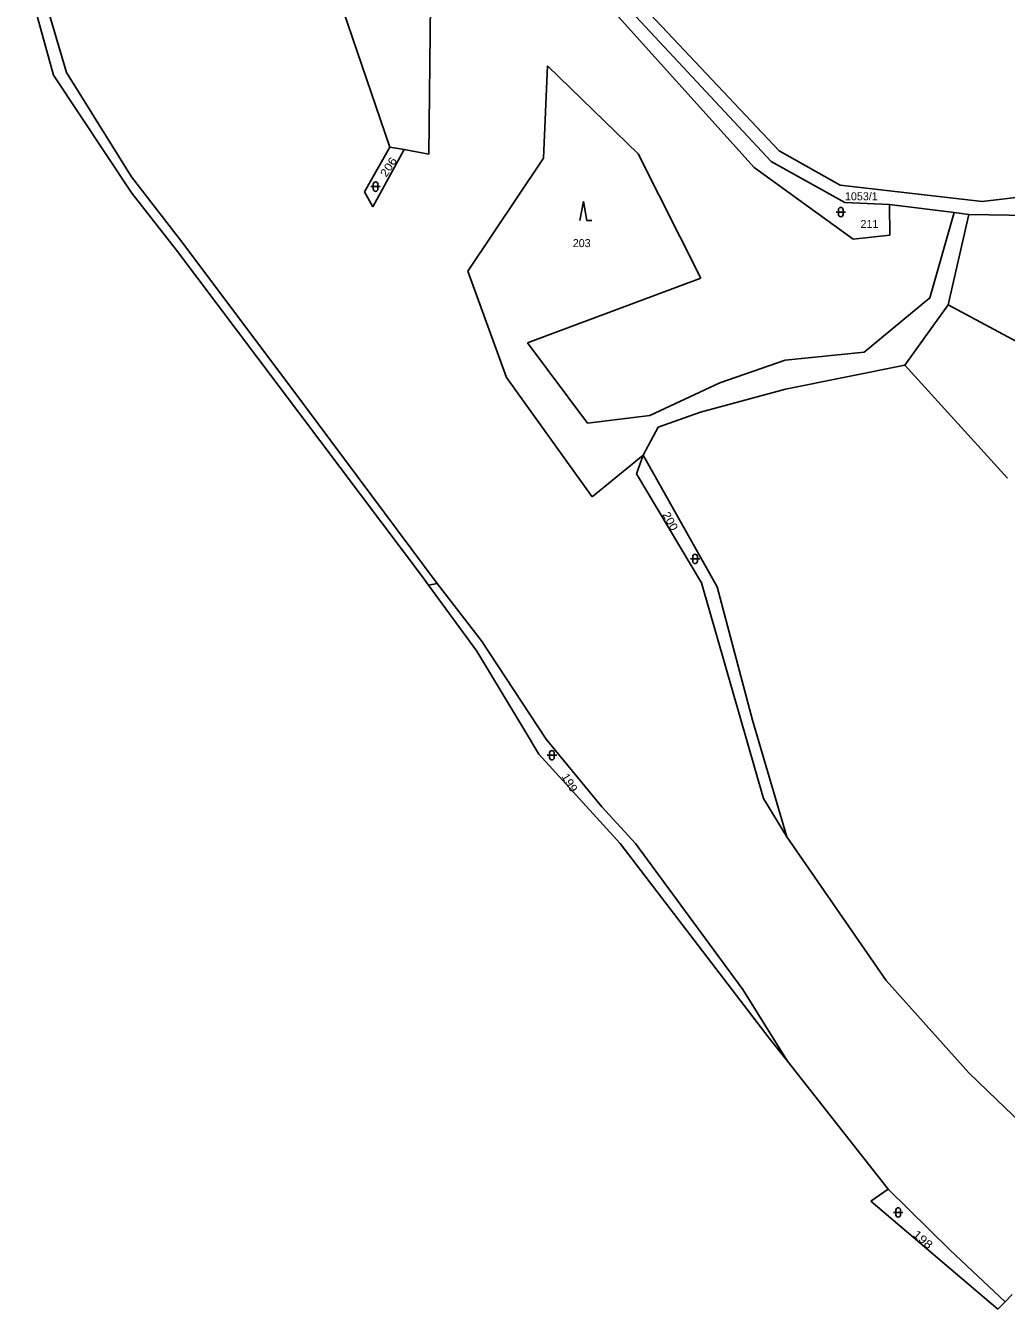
# Model space of a CAD drawing. Extents: x -744132 to -742433, y -984679 to -982287.
# Drawn here: x -743199.3 to -742991, y -984512.6 to -984240 of the extents above; entities that cross this region are included whole.
import ezdxf

# ---------------------------------------------------------------- set-up
doc = ezdxf.new("R2010")
doc.units = 0
doc.header["$LTSCALE"] = 0.68
doc.layers.add('1', color=7, linetype='Continuous', lineweight=25)
doc.layers.add('3', color=7, linetype='Continuous', lineweight=25)
doc.layers.add('2', color=7, linetype='Continuous')

msp = doc.modelspace()

# ---------------------------------------------------------------- linework, layer by layer
at = {"layer": '1'}
for p, q in [((-743190.62, -984249.97), (-743198.06, -984224.85)), ((-743079.78, -984227.24), (-743040.94, -984268.88)), ((-743199.32, -984229.05), (-743193.39, -984250.57)), ((-743134.8, -984228.15), (-743121.95, -984265.83)), ((-743073.53, -984230.29), (-743039.24, -984266.63)), ((-743079.06, -984231.79), (-743044.54, -984270.13)), ((-743113.67, -984267.35), (-743113.33, -984235.31)), ((-743088.46, -984248.53), (-743089.29, -984268.15)), ((-743069.21, -984267.24), (-743088.46, -984248.53)), ((-743193.39, -984250.57), (-743176.73, -984275.57)), ((-743176.87, -984272.12), (-743190.62, -984249.97)), ((-743121.95, -984265.83), (-743127.33, -984275.33)), ((-743125.59, -984278.51), (-743118.89, -984266.36)), ((-743121.95, -984265.83), (-743118.89, -984266.36)), ((-743118.89, -984266.36), (-743113.67, -984267.35)), ((-743089.29, -984268.15), (-743105.41, -984292.13)), ((-743055.92, -984293.65), (-743069.21, -984267.24)), ((-743039.24, -984266.63), (-743026.29, -984273.89)), ((-743044.54, -984270.13), (-743023.52, -984285.4)), ((-743040.94, -984268.88), (-743025.3, -984277.56)), ((-743165.92, -984286.22), (-743176.87, -984272.12)), ((-743026.29, -984273.89), (-742996.15, -984277.35)), ((-743176.73, -984275.57), (-743167.29, -984287.69)), ((-743127.33, -984275.33), (-743125.59, -984278.51)), ((-742996.15, -984277.35), (-742986.54, -984276.26)), ((-743025.3, -984277.56), (-743015.82, -984277.98)), ((-743015.7, -984284.55), (-743015.82, -984277.98)), ((-743015.82, -984277.98), (-743002.06, -984279.73)), ((-743002.06, -984279.73), (-743007.23, -984297.79)), ((-743003.32, -984299.32), (-742998.92, -984280.13)), ((-743002.06, -984279.73), (-742998.92, -984280.13)), ((-742998.92, -984280.13), (-742986.17, -984280.32)), ((-743023.52, -984285.4), (-743015.7, -984284.55)), ((-743140.1, -984320.72), (-743165.92, -984286.22)), ((-743167.29, -984287.69), (-743115.24, -984356.81)), ((-743105.41, -984292.13), (-743097.16, -984314.76)), ((-743092.72, -984307.41), (-743055.92, -984293.65)), ((-743007.23, -984297.79), (-743021.17, -984309.37)), ((-743012.53, -984312.09), (-743003.32, -984299.32)), ((-743003.32, -984299.32), (-742985.75, -984308.73)), ((-743079.93, -984324.44), (-743092.72, -984307.41)), ((-743037.99, -984311.09), (-743051.88, -984315.86)), ((-743021.17, -984309.37), (-743037.99, -984311.09)), ((-743037.88, -984317.21), (-743012.53, -984312.09)), ((-743012.53, -984312.09), (-742990.72, -984336.15)), ((-743097.16, -984314.76), (-743078.96, -984340.1)), ((-743051.88, -984315.86), (-743066.72, -984322.78)), ((-743055.99, -984322.09), (-743037.88, -984317.21)), ((-743111.92, -984358.52), (-743140.1, -984320.72)), ((-743066.72, -984322.78), (-743079.93, -984324.44)), ((-743064.96, -984325.28), (-743055.99, -984322.09)), ((-743068.16, -984331.26), (-743064.96, -984325.28)), ((-743078.96, -984340.1), (-743068.16, -984331.26)), ((-743068.16, -984331.26), (-743069.58, -984335.2)), ((-743052.42, -984359.19), (-743068.16, -984331.26)), ((-743069.58, -984335.2), (-743055.74, -984358.36)), ((-743115.24, -984356.81), (-743113.75, -984358.85)), ((-743055.74, -984358.36), (-743042.57, -984404.16)), ((-743113.75, -984358.85), (-743111.92, -984358.52)), ((-743113.75, -984358.85), (-743103.5, -984372.84)), ((-743111.92, -984358.52), (-743102.48, -984370.67)), ((-743044.93, -984387.48), (-743052.42, -984359.19)), ((-743102.48, -984370.67), (-743088.71, -984391.55)), ((-743103.5, -984372.84), (-743092.9, -984390.37)), ((-743037.63, -984412.31), (-743044.93, -984387.48)), ((-743092.9, -984390.37), (-743090.29, -984394.7)), ((-743088.71, -984391.55), (-743076.89, -984405.91)), ((-743090.29, -984394.7), (-743073.04, -984413.72)), ((-743042.57, -984404.16), (-743037.63, -984412.31)), ((-743076.89, -984405.91), (-743069.77, -984413.68)), ((-743016.49, -984442.82), (-743037.63, -984412.31)), ((-743073.04, -984413.72), (-743041.37, -984455.03)), ((-743069.77, -984413.68), (-743046.98, -984444.7)), ((-742998.92, -984462.38), (-743016.49, -984442.82)), ((-743046.98, -984444.7), (-743037.51, -984459.93)), ((-743041.37, -984455.03), (-743037.51, -984459.93)), ((-743037.51, -984459.93), (-743016.12, -984487.08)), ((-742992.99, -984468.09), (-742998.92, -984462.38)), ((-742978.22, -984482.31), (-742992.99, -984468.09)), ((-743016.12, -984487.08), (-743019.79, -984489.66)), ((-743016.12, -984487.08), (-743002.95, -984500.08)), ((-743019.79, -984489.66), (-742992.8, -984512.61)), ((-743002.95, -984500.08), (-742991.25, -984511.01)), ((-742992.8, -984512.61), (-742991.25, -984511.01)), ((-742991.25, -984511.01), (-742989.77, -984509.49))]:
    msp.add_line(p, q, dxfattribs=at)
at = {"layer": '3'}
for p, q in [((-743125.481, -984273.711), (-743125.481, -984274.712)), ((-743124.479, -984274.712), (-743124.479, -984273.711)), ((-743125.981, -984274.211), (-743123.979, -984274.211)), ((-743026.661, -984279.121), (-743026.661, -984280.122)), ((-743025.659, -984280.122), (-743025.659, -984279.121)), ((-743080.07, -984281.39), (-743079.074, -984281.39)), ((-743027.161, -984279.621), (-743025.159, -984279.621)), ((-743057.611, -984352.771), (-743057.611, -984353.772)), ((-743056.609, -984353.772), (-743056.609, -984352.771)), ((-743058.111, -984353.271), (-743056.109, -984353.271)), ((-743088.511, -984394.951), (-743086.509, -984394.951)), ((-743088.011, -984394.451), (-743088.011, -984395.452)), ((-743087.009, -984395.452), (-743087.009, -984394.451)), ((-743014.451, -984491.531), (-743014.451, -984492.532)), ((-743013.449, -984492.532), (-743013.449, -984491.531)), ((-743014.951, -984492.031), (-743012.949, -984492.031))]:
    msp.add_line(p, q, dxfattribs=at)
msp.add_lwpolyline([(-743080.07, -984281.39), (-743080.82, -984277.39), (-743081.57, -984281.39)], dxfattribs=at)
for centre, start, end in [((-743124.98, -984273.7109), 0, 180), ((-743124.98, -984274.7109), 180, 359.98789), ((-743026.16, -984279.1209), 0, 180), ((-743026.16, -984280.1209), 180, 359.98789), ((-743057.11, -984352.7709), 0, 180), ((-743057.11, -984353.7709), 180, 359.98789), ((-743087.51, -984394.4509), 0, 180), ((-743087.51, -984395.4509), 180, 359.98789), ((-743013.95, -984491.5309), 0, 180), ((-743013.95, -984492.5309), 180, 359.98789)]:
    msp.add_arc(centre, 0.5, start, end, dxfattribs=at)

# ---------------------------------------------------------------- texts
at = {"layer": '2'}
for s, rotation, width, p in [('206', 57, 1.15, (-743122.713, -984272.331)), ('200', 299, 1.1, (-743064.121, -984343.816)), ('199', 301, 1.1, (-743085.554, -984399.408)), ('198', 319, 1.2, (-743010.968, -984496.92))]:
    msp.add_text(s, height=1.7, rotation=rotation, dxfattribs=dict(at, width=width)).set_placement(p)
for s, p in [('1053/1', (-743025.26, -984277.115)), ('211', (-743021.96, -984282.995)), ('203', (-743083.09, -984287.055))]:
    msp.add_text(s, height=1.7, dxfattribs=at).set_placement(p)

doc.saveas('drawing.dxf')
